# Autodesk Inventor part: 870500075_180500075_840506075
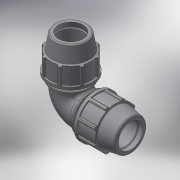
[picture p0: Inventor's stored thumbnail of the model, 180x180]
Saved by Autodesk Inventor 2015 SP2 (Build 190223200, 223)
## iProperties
Created: 2017-02
Part Number: 870500075_180500075_840506075
Material: Generic
Description: PLASSON 90° ELBOW 75-75
Document SubType Name: Modeling
Designer: KIM
Mass: 1923.39 g
Surface Area: 2516.77 cm^2
Volume: 1923.39 cm^3
Density: 1 g/cm^3
Appearance: Default
Author: KIM
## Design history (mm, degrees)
derived "87050.ipt"
feature "Solid1::87050.ipt"
tag "TaggingFeature1"
body "Solid1"
other parameters: "d2" = 75, "d4" = 15.33333, "d5" = 46, "d7" = 132, "d9" = 26.28571, "d11" = 6.13333, "d13" = 120 deg, "d14" = 97.5, "d15" = 10 deg, "d16" = 114.84, "d18" = 3.75, "d19" = 35 deg, "d20" = 17.5 deg, "d21" = 122.76, "d23" = 0, "d25" = 360 deg, "d27" = 2.64, "d33" = 1.5, "d42" = 62.56, "d43" = 3.96, "d46" = 2.25, "d51" = 184, "d59" = 90 deg, "d63" = 137, "d64" = 67.5, "d67" = 99, "d68" = 11.04, "d70" = 90 deg, "d71" = 11.25, "d72" = 8.8, "d73" = 0, "d75" = 90 deg, "d77" = 112.5432, "d78" = 3.68, "d_" = 75, "E_" = 132, "A_" = 184, "l_" = 137
